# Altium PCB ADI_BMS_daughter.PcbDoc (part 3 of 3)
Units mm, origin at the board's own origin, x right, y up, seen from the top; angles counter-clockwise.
Board outline 140 x 50 mm, 4 copper layers (Top Layer, Layer 1, Layer 2, Bottom Layer), stack 1.586 mm thick; 306 components, 232 nets, 866 pads, 333 vias.
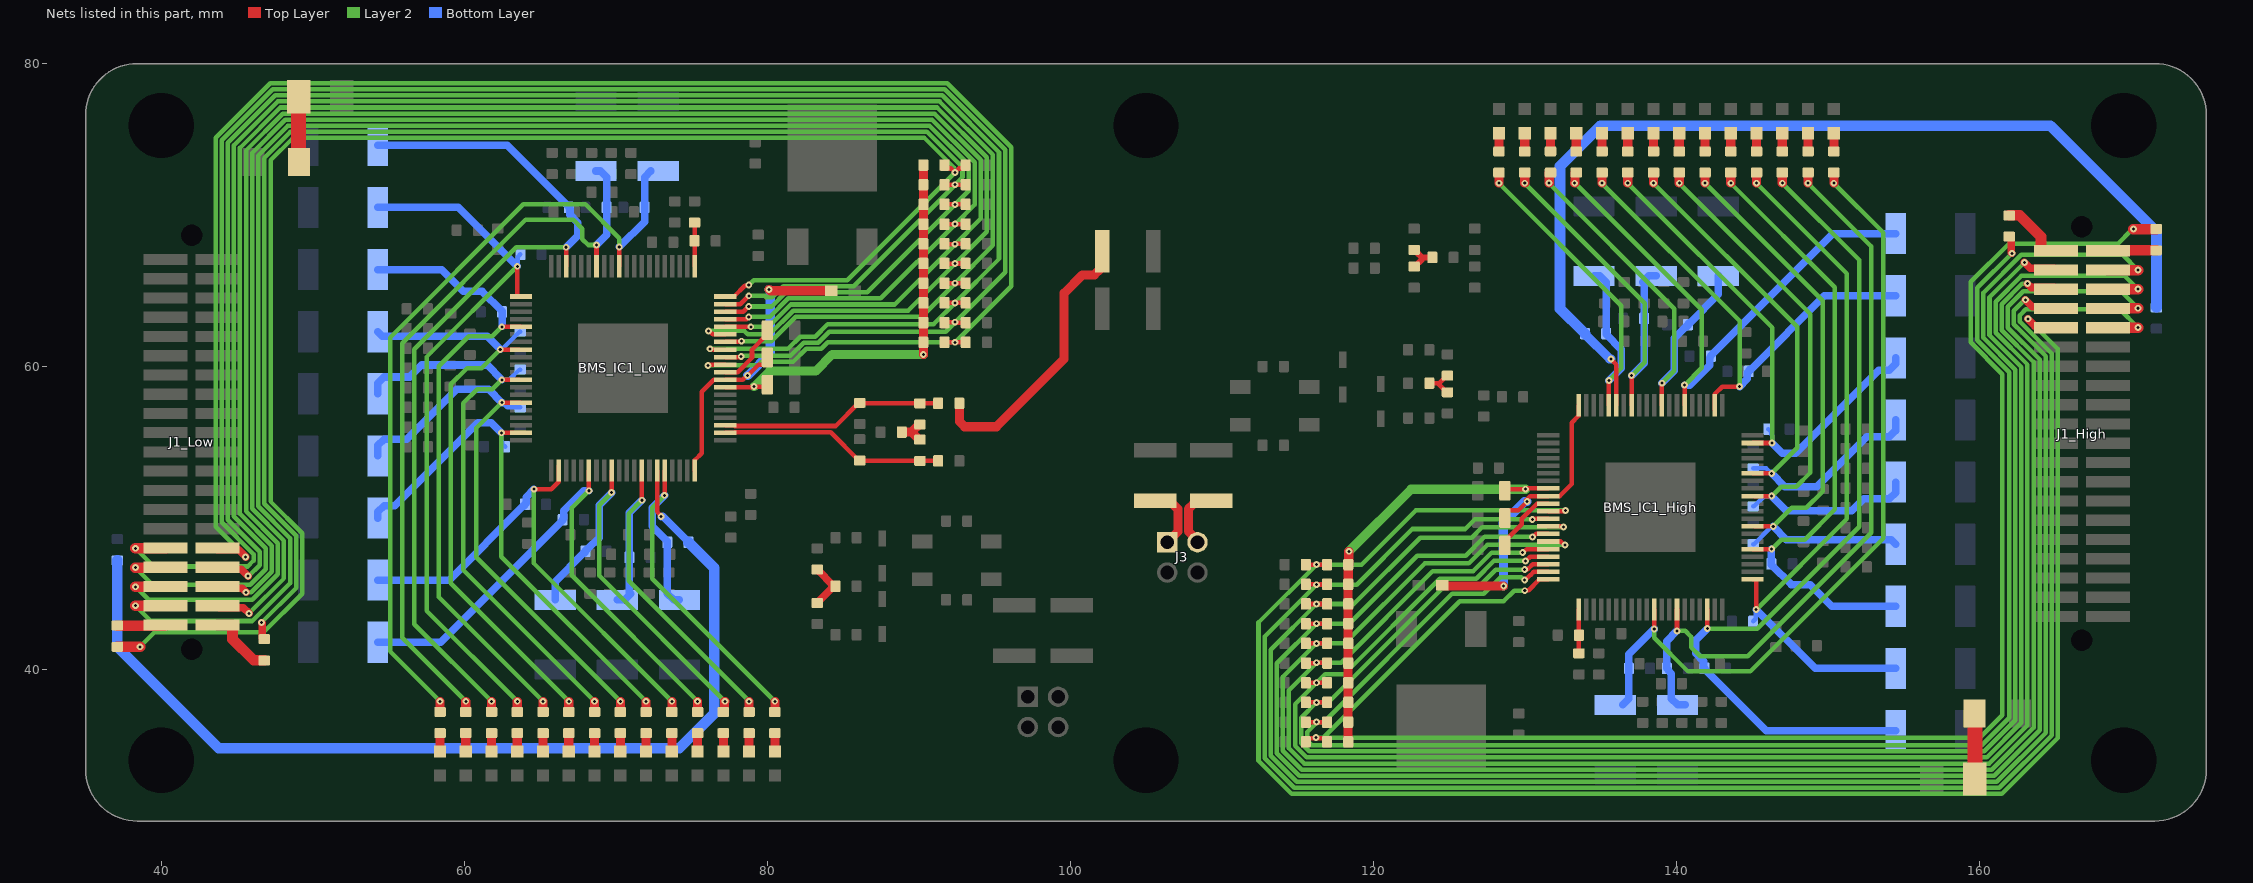
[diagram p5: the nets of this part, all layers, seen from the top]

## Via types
v1: diameter 0.45, hole 0.2, Top Layer to Bottom Layer, tented both sides, 226 vias
v2: diameter 0.5, hole 0.2, Top Layer to Bottom Layer, tented both sides, 105 vias
v3: diameter 2, hole 0.5, Top Layer to Bottom Layer, tented both sides, 2 vias

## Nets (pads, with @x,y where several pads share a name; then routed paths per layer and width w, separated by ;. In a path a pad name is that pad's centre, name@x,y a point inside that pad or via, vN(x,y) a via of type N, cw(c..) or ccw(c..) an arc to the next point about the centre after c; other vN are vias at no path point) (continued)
IB_Low_Intr_P: C55.2 R76.1 | length 18.7
  Top Layer w0.6: R76.1@92.679,57.571 92.679,56.374 93.03,56.022 95.122,56.022 99.598,60.498 99.598,64.841 100.808,66.051 101.597,66.051 101.948,66.402 101.948,67.423 C55.2@102.125,67.6
IB_Low_N: BMS_IC1_Low.62 C52.1 R73.1 R75.2 | length 14.9
  Top Layer w0.3: BMS_IC1_Low.62@77.217,55.621 77.804,55.621 77.853,55.671 84.18,55.671 86.05,53.8 C52.1@86.1,53.8 86.114,53.786 90.064,53.786 R73.1@90.079,53.771 R75.2@91.279,53.771
IB_Low_P: BMS_IC1_Low.63 C53.2 R74.2 R76.2 | length 14.7
  Top Layer w0.3: BMS_IC1_Low.63@77.217,56.121 77.804,56.121 77.853,56.072 84.522,56.072 86.05,57.6 C53.2@86.1,57.6 86.114,57.586 90.064,57.586 R74.2@90.079,57.571 R76.2@91.279,57.571
IB_Out_N: C60.2 J3.1 | length 4.2
  Top Layer w0.6: C60.2@105.6,51.125 105.777,50.948 106.749,50.948 107.1,50.597 107.1,49.1 J3.1@106.4,48.4
IB_Out_P: C62.2 J3.3 | length 4.2
  Top Layer w0.6: J3.3@108.4,48.4 108.4,48.528 107.802,49.126 107.802,50.597 108.153,50.948 109.123,50.948 C62.2@109.3,51.125
NetC48_1: C48.1 R68.1 R70.2 | length 3.1
  Top Layer w0.5: R70.2@83.3,44.4 83.35,44.4 83.43,44.48 83.43,44.53 84.27,45.37 84.27,45.63 83.43,46.47 83.43,46.52 83.35,46.6 R68.1@83.3,46.6
NetC51_2: C51.2 R73.2 R74.1 | length 2
  Top Layer w0.6: C51.2@88.879,55.671 89.609,55.671 ; 89.609,55.591 90.029,55.171 R73.2@90.079,55.171 ; 89.609,55.751 90.029,56.171 R74.1@90.079,56.171
NetC56_1: C56.1 R79.2 R80.2 | length 2.3
  Top Layer w0.4: R80.2@122.7,66.6 122.75,66.6 123.2,67.05 123.2,67.2 ; R79.2@122.7,67.7 122.75,67.7 122.966,67.484 122.966,67.434 123.2,67.2 ; C56.1@123.9,67.2 123.2,67.2
NetC61_1: C61.1 R82.1 R85.2 | length 2.5
  Top Layer w0.3: C61.1@123.7,58.9 124.2,58.9 ; R85.2@124.9,58.3 124.85,58.3 124.25,58.9 124.2,58.9 ; R82.1@124.9,59.4 124.85,59.4 124.35,58.9 124.2,58.9
  Top Layer w0.5: C61.1@123.7,58.9 C61.1@123.78,58.82
NetD1_High_1: D1_High.1 R42_High.1 | length 1.2
  Top Layer w0.6: R42_High.1@128.3,74.2 D1_High.1@128.3,75.4
NetD1_Low_1: D1_Low.1 R42_Low.1 | length 1.2
  Top Layer w0.6: D1_Low.1@80.5,34.6 R42_Low.1@80.5,35.8
NetD2_High_1: D2_High.1 R43_High.1 | length 1.2
  Top Layer w0.6: R43_High.1@130,74.2 D2_High.1@130,75.4
NetD2_Low_1: D2_Low.1 R43_Low.1 | length 1.2
  Top Layer w0.6: D2_Low.1@78.8,34.6 R43_Low.1@78.8,35.8
NetD3_High_1: D3_High.1 R44_High.1 | length 1.2
  Top Layer w0.6: R44_High.1@131.7,74.2 D3_High.1@131.7,75.4
NetD3_Low_1: D3_Low.1 R44_Low.1 | length 1.2
  Top Layer w0.6: D3_Low.1@77.1,34.6 R44_Low.1@77.1,35.8
NetD4_High_1: D4_High.1 R45_High.1 | length 1.2
  Top Layer w0.6: R45_High.1@133.4,74.2 D4_High.1@133.4,75.4
NetD4_Low_1: D4_Low.1 R45_Low.1 | length 1.2
  Top Layer w0.6: D4_Low.1@75.4,34.6 R45_Low.1@75.4,35.8
NetD5_High_1: D5_High.1 R46_High.1 | length 1.2
  Top Layer w0.6: R46_High.1@135.1,74.2 D5_High.1@135.1,75.4
NetD5_Low_1: D5_Low.1 R46_Low.1 | length 1.2
  Top Layer w0.6: D5_Low.1@73.7,34.6 R46_Low.1@73.7,35.8
NetD6_High_1: D6_High.1 R47_High.1 | length 1.2
  Top Layer w0.6: R47_High.1@136.8,74.2 D6_High.1@136.8,75.4
NetD6_Low_1: D6_Low.1 R47_Low.1 | length 1.2
  Top Layer w0.6: D6_Low.1@72,34.6 R47_Low.1@72,35.8
NetD7_High_1: D7_High.1 R48_High.1 | length 1.2
  Top Layer w0.6: R48_High.1@138.5,74.2 D7_High.1@138.5,75.4
NetD7_Low_1: D7_Low.1 R48_Low.1 | length 1.2
  Top Layer w0.6: D7_Low.1@70.3,34.6 R48_Low.1@70.3,35.8
NetD8_High_1: D8_High.1 R56_High.1 | length 1.2
  Top Layer w0.6: R56_High.1@140.2,74.2 D8_High.1@140.2,75.4
NetD8_Low_1: D8_Low.1 R56_Low.1 | length 1.2
  Top Layer w0.6: D8_Low.1@68.6,34.6 R56_Low.1@68.6,35.8
NetD9_High_1: D9_High.1 R57_High.1 | length 1.2
  Top Layer w0.6: R57_High.1@141.9,74.2 D9_High.1@141.9,75.4
NetD9_Low_1: D9_Low.1 R57_Low.1 | length 1.2
  Top Layer w0.6: D9_Low.1@66.9,34.6 R57_Low.1@66.9,35.8
NetD10_High_1: D10_High.1 R58_High.1 | length 1.2
  Top Layer w0.6: R58_High.1@143.6,74.2 D10_High.1@143.6,75.4
NetD10_Low_1: D10_Low.1 R58_Low.1 | length 1.2
  Top Layer w0.6: D10_Low.1@65.2,34.6 R58_Low.1@65.2,35.8
NetD11_High_1: D11_High.1 R59_High.1 | length 1.2
  Top Layer w0.6: R59_High.1@145.3,74.2 D11_High.1@145.3,75.4
NetD11_Low_1: D11_Low.1 R59_Low.1 | length 1.2
  Top Layer w0.6: D11_Low.1@63.5,34.6 R59_Low.1@63.5,35.8
NetD12_High_1: D12_High.1 R60_High.1 | length 1.2
  Top Layer w0.6: R60_High.1@147,74.2 D12_High.1@147,75.4
NetD12_Low_1: D12_Low.1 R60_Low.1 | length 1.2
  Top Layer w0.6: D12_Low.1@61.8,34.6 R60_Low.1@61.8,35.8
NetD13_High_1: D13_High.1 R61_High.1 | length 1.2
  Top Layer w0.6: R61_High.1@148.7,74.2 D13_High.1@148.7,75.4
NetD13_Low_1: D13_Low.1 R61_Low.1 | length 1.2
  Top Layer w0.6: D13_Low.1@60.1,34.6 R61_Low.1@60.1,35.8
NetD14_High_1: D14_High.1 R62_High.1 | length 1.2
  Top Layer w0.6: R62_High.1@150.4,74.2 D14_High.1@150.4,75.4
NetD14_Low_1: D14_Low.1 R62_Low.1 | length 1.2
  Top Layer w0.6: D14_Low.1@58.4,34.6 R62_Low.1@58.4,35.8
NetD15_High_1: D15_High.1 R63_High.2 | length 4.3
  Top Layer w1: D15_High.1@159.704,32.771 159.716,32.784 159.716,37.059 R63_High.2@159.729,37.071
NetD15_Low_1: D15_Low.1 R63_Low.2 | length 4.3
  Top Layer w1: R63_Low.2@49.05,73.5 49.062,73.512 49.062,77.787 D15_Low.1@49.075,77.8
S1N_High: BMS_IC1_High.55 C25_High.1 R34_High.1 | length 65.8
  Top Layer w0.3: v1(135.7,60.5) 135.7,60.459 136.054,60.105 136.054,58.654 136.05,58.65 BMS_IC1_High.55@136.05,57.438
  Bottom Layer w0.6: C25_High.1@133.979,62.171 133.979,62.121 135.6,60.5 v1(135.7,60.5)
  Bottom Layer w0.7: C25_High.1@133.979,62.171 133.959,62.191 133.959,62.201 133.939,62.221 133.929,62.221 132.329,63.821 132.329,73.229 135,75.9 164.7,75.9 171.7,68.9 R34_High.1@171.7,63.9
S1N_Low: BMS_IC1_Low.55 C25_Low.1 R34_Low.1 | length 66.5
  Top Layer w0.3: BMS_IC1_Low.55@72.729,53.133 72.729,51.712 72.725,51.708 72.725,50.416 73,50.141 v1(73,50.1)
  Bottom Layer w0.5: v1(73,50.1) 73.1,50.1 74.67,48.53 74.72,48.53 74.8,48.45 C25_Low.1@74.8,48.4
  Bottom Layer w0.7: R34_Low.1@37.1,47.2 37.1,41.5 43.8,34.8 74.2,34.8 76.5,37.1 76.5,46.7 74.85,48.35 74.84,48.35 74.82,48.37 74.82,48.38 C25_Low.1@74.8,48.4
S1P_High: BMS_IC1_High.56 C25_High.2 R35_High.2 R42_High.2 | length 27.5
  Top Layer w0.3: BMS_IC1_High.56@135.55,57.438 135.55,59.069 v1(135.552,59.071)
  Top Layer w0.6: v1(128.3,72.1) R42_High.2@128.3,72.8
  Layer 2 w0.3: v1@128.251,72.149 136.379,64.021 136.379,59.898 v1(135.552,59.071)
  Bottom Layer w0.5: R35_High.2@134.679,65.877 R35_High.2@134.579,65.977 134.964,65.977 135.379,65.562 C25_High.2@135.379,62.171 135.379,62.121 136.379,61.121 136.379,59.898 v1(135.552,59.071)
S1P_Low: BMS_IC1_Low.56 C25_Low.2 R35_Low.2 R42_Low.2 | length 27.9
  Top Layer w0.3: v1(73.227,51.5) 73.229,51.502 BMS_IC1_Low.56@73.229,53.133
  Top Layer w0.6: R42_Low.2@80.5,37.2 v1(80.5,37.9)
  Layer 2 w0.3: v1(73.227,51.5) 72.4,50.673 72.4,46 v1(80.5,37.9)
  Bottom Layer w0.5: v1(73.227,51.5) 72.4,50.673 72.4,50.351 72.398,50.349 72.398,49.851 72.4,49.849 72.4,49.45 73.4,48.45 C25_Low.2@73.4,48.4 73.4,45.009 73.815,44.594 R35_Low.2@74.2,44.594
S2P_High: BMS_IC1_High.53 C26_High.2 R36_High.2 R43_High.2 | length 27.1
  Top Layer w0.3: BMS_IC1_High.53@137.05,57.438 137.05,59.398 v1(137.052,59.4)
  Top Layer w0.6: v1(130,72.1) R43_High.2@130,72.8
  Layer 2 w0.3: v1@129.995,72.105 137.929,64.171 137.929,60.277 v1(137.052,59.4)
  Bottom Layer w0.5: v1(137.052,59.4) 137.879,60.227 C26_High.2@137.879,63.171 137.879,65.662 R36_High.2@138.194,65.977 ; R36_High.2@137.779,65.562 R36_High.2@138.194,65.977 ; R36_High.2@138.679,65.977 R36_High.2@138.194,65.977
S2P_Low: BMS_IC1_Low.53 C26_Low.2 R36_Low.2 R43_Low.2 | length 27.7
  Top Layer w0.3: v1(71.727,51.171) 71.729,51.173 BMS_IC1_Low.53@71.729,53.133
  Top Layer w0.6: R43_Low.2@78.8,37.2 v1(78.8,37.9)
  Layer 2 w0.3: v1(71.727,51.171) 70.85,50.295 70.85,45.85 v1(78.8,37.9)
  Bottom Layer w0.5: R36_Low.2@70.1,44.594 R36_Low.2@70.585,44.594 ; R36_Low.2@71,45.009 R36_Low.2@70.585,44.594 ; v1(71.727,51.171) 70.9,50.345 C26_Low.2@70.9,47.4 70.9,44.909 R36_Low.2@70.585,44.594
S3P_High: BMS_IC1_High.49 C27_High.2 R37_High.2 R44_High.2 | length 27.8
  Top Layer w0.3: BMS_IC1_High.49@139.05,57.438 139.05,58.894 v1(139.052,58.896)
  Top Layer w0.6: v1(131.604,72.106) 131.62,72.122 131.62,72.77 131.65,72.8 R44_High.2@131.7,72.8
  Layer 2 w0.3: v1@131.598,72.102 139.879,63.821 139.879,59.723 v1(139.052,58.896)
  Bottom Layer w0.5: v1(139.052,58.896) 139.879,59.723 139.879,61.871 140.649,62.641 140.699,62.641 C27_High.2@140.779,62.721 ; C27_High.2@140.779,62.771 140.779,62.821 140.859,62.901 140.909,62.901 142.779,64.771 R37_High.2@142.779,65.977
S3P_Low: BMS_IC1_Low.49 C27_Low.2 R37_Low.2 R44_Low.2 | length 28.4
  Top Layer w0.3: v1(69.727,51.675) 69.729,51.677 BMS_IC1_Low.49@69.729,53.133
  Top Layer w0.6: R44_Low.2@77.1,37.2 77.15,37.2 77.18,37.23 77.18,37.878 v1(77.202,37.9)
  Layer 2 w0.3: v1(69.727,51.675) 68.9,50.848 68.9,46.202 v1(77.202,37.9)
  Bottom Layer w0.5: R37_Low.2@66,44.594 66,45.8 67.87,47.67 67.92,47.67 68,47.75 C27_Low.2@68,47.8 ; C27_Low.2@68,47.85 68.08,47.93 68.13,47.93 68.9,48.7 68.9,50.848 v1(69.727,51.675)
S4P_High: BMS_IC1_High.46 C28_High.2 R38_High.2 R45_High.2 | length 37.8
  Top Layer w0.3: BMS_IC1_High.46@140.55,57.438 v1(140.552,58.771) v1(140.552,58.771)
  Top Layer w0.6: v1(133.298,72.1) 133.32,72.122 133.32,72.77 133.37,72.77 R45_High.2@133.4,72.8
  Layer 2 w0.3: v1(133.298,72.1) 133.325,72.1 141.689,63.736 141.689,59.909 v1(140.552,58.771)
  Bottom Layer w0.5: v1(140.552,58.771) 140.879,58.771 142.198,60.091 142.198,60.591 C28_High.2@142.279,60.671 142.279,60.721 150.329,68.771 R38_High.2@154.485,68.771
S4P_Low: BMS_IC1_Low.46 C28_Low.2 R38_Low.2 R45_Low.2 | length 38.2
  Top Layer w0.3: v1(68.227,51.8) 68.229,51.802 BMS_IC1_Low.46@68.229,53.133
  Top Layer w0.6: R45_Low.2@75.4,37.2 v1(75.4,37.9)
  Layer 2 w0.3: v1(68.227,51.8) 67.089,50.663 67.089,46.211 v1(75.4,37.9)
  Bottom Layer w0.5: R38_Low.2@54.294,41.8 58.45,41.8 66.5,49.85 C28_Low.2@66.5,49.9 66.58,49.98 66.58,50.48 67.9,51.8 v1(68.227,51.8)
S5P_High: BMS_IC1_High.42 C29_High.2 R39_High.2 R46_High.2 | length 33.8
  Top Layer w0.3: BMS_IC1_High.42@142.55,57.138 142.55,58.181 143.04,58.671 v1(144.179,58.671)
  Top Layer w0.6: v1(135.1,72.1) R46_High.2@135.1,72.8
  Layer 2 w0.3: v1@135.092,72.108 144.179,63.021 v1(144.179,58.671)
  Bottom Layer w0.5: v1(144.179,58.671) 144.699,59.191 144.699,59.591 C29_High.2@144.779,59.671 144.779,59.721 144.859,59.801 144.909,59.801 149.779,64.671 R39_High.2@154.485,64.671
S5P_Low: BMS_IC1_Low.42 C29_Low.2 R39_Low.2 R46_Low.2 | length 34.4
  Top Layer w0.3: v1(64.6,51.9) 65.739,51.9 66.229,52.39 BMS_IC1_Low.42@66.229,53.433
  Top Layer w0.6: R46_Low.2@73.7,37.2 v1(73.7,37.9)
  Layer 2 w0.3: v1(64.6,51.9) 64.6,47 v1(73.7,37.9)
  Bottom Layer w0.5: R39_Low.2@54.294,45.9 59,45.9 63.87,50.77 63.92,50.77 64,50.85 C29_Low.2@64,50.9 64.08,50.98 64.08,51.38 v1(64.6,51.9)
S6P_High: BMS_IC1_High.39 C30_High.2 R40_High.2 R47_High.2 | length 35.4
  Top Layer w0.3: BMS_IC1_High.39@145.038,54.95 146.327,54.95 v1(146.329,54.948)
  Top Layer w0.6: v1(136.8,72.1) R47_High.2@136.8,72.8
  Layer 2 w0.3: v1@136.827,72.073 146.329,62.571 v1(146.329,54.948)
  Bottom Layer w0.3: C30_High.2@146.079,55.871 146.259,55.691 146.259,55.535 146.329,55.466 v1(146.329,54.948)
  Bottom Layer w0.5: v1(146.329,54.948) 147.005,54.271 147.879,54.271 153.363,59.755 154.07,59.755 154.485,60.17 R40_High.2@154.485,60.571
S6P_Low: BMS_IC1_Low.39 C30_Low.2 R40_Low.2 R47_Low.2 | length 36
  Top Layer w0.3: v1(62.45,55.623) 62.452,55.621 BMS_IC1_Low.39@63.741,55.621
  Top Layer w0.6: R47_Low.2@72,37.2 v1(72,37.9)
  Layer 2 w0.3: v1(62.45,55.623) 62.45,47.45 v1(72,37.9)
  Bottom Layer w0.3: v1(62.45,55.623) 62.45,55.106 62.52,55.036 62.52,54.88 C30_Low.2@62.7,54.7
  Bottom Layer w0.5: R40_Low.2@54.294,50 54.294,50.401 54.709,50.816 55.416,50.816 60.9,56.3 61.773,56.3 v1(62.45,55.623)
S7P_High: BMS_IC1_High.35 C31_High.2 R41_High.2 R48_High.2 | length 37.8
  Top Layer w0.3: BMS_IC1_High.35@145.038,52.95 v1(146.3,52.948) v1(146.3,52.948)
  Top Layer w0.6: v1(138.5,72.1) R48_High.2@138.5,72.8
  Layer 2 w0.3: v1@138.549,72.051 147.981,62.619 147.981,54.629 v1(146.3,52.948)
  Bottom Layer w0.3: C31_High.2@145.079,53.271 145.936,53.271 146.259,52.948 v1(146.3,52.948)
  Bottom Layer w0.5: v1(146.3,52.948) 147.176,52.071 149.279,52.071 152.569,55.361 154.07,55.361 154.485,55.776 R41_High.2@154.485,56.471
S7P_Low: BMS_IC1_Low.35 C31_Low.2 R41_Low.2 R48_Low.2 | length 38.5
  Top Layer w0.3: v1(62.479,57.623) 62.481,57.621 BMS_IC1_Low.35@63.741,57.621
  Top Layer w0.6: R48_Low.2@70.3,37.2 v1(70.3,37.9)
  Layer 2 w0.3: v1(62.479,57.623) 60.798,55.942 60.798,47.402 v1(70.3,37.9)
  Bottom Layer w0.3: v1(62.479,57.623) 62.52,57.623 62.843,57.3 C31_Low.2@63.7,57.3
  Bottom Layer w0.5: R41_Low.2@54.294,54.1 54.294,54.795 54.709,55.21 56.21,55.21 59.5,58.5 61.602,58.5 v1(62.479,57.623)
S8P_High: BMS_IC1_High.32 C32_High.2 R49_High.2 R56_High.2 | length 39
  Top Layer w0.3: BMS_IC1_High.32@145.138,51.45 146.298,51.45 v1(146.3,51.448)
  Top Layer w0.6: v1(140.2,72.1) R56_High.2@140.2,72.8
  Layer 2 w0.3: v1@140.208,72.092 148.858,63.442 148.858,53.001 147.929,52.071 146.923,52.071 v1(146.3,51.448)
  Bottom Layer w0.3: C32_High.2@145.079,50.771 145.128,50.771 145.805,51.448 v1(146.3,51.448)
  Bottom Layer w0.5: v1(146.3,51.448) 147.277,50.471 151.579,50.471 152.369,51.261 154.07,51.261 154.485,51.676 R49_High.2@154.485,52.371
S8P_Low: BMS_IC1_Low.32 C32_Low.2 R49_Low.2 R56_Low.2 | length 39.6
  Top Layer w0.3: v1(62.479,59.123) 62.481,59.121 BMS_IC1_Low.32@63.641,59.121
  Top Layer w0.6: R56_Low.2@68.6,37.2 v1(68.6,37.9)
  Layer 2 w0.3: v1(62.479,59.123) 61.855,58.5 60.85,58.5 59.921,57.571 59.921,46.579 v1(68.6,37.9)
  Bottom Layer w0.3: v1(62.479,59.123) 62.974,59.123 63.65,59.8 C32_Low.2@63.7,59.8
  Bottom Layer w0.5: R49_Low.2@54.294,58.2 54.294,58.895 54.709,59.31 56.41,59.31 57.2,60.1 61.502,60.1 v1(62.479,59.123)
S9P_High: BMS_IC1_High.28 C33_High.2 R50_High.2 R57_High.2 | length 40.1
  Top Layer w0.3: BMS_IC1_High.28@145.138,49.45 146.398,49.45 v1(146.403,49.445)
  Top Layer w0.6: v1(141.9,72.1) R57_High.2@141.9,72.8
  Layer 2 w0.3: v1@141.905,72.095 149.661,64.339 149.661,51.754 148.579,50.671 147.63,50.671 v1(146.403,49.445)
  Bottom Layer w0.3: C33_High.2@145.079,48.271 145.128,48.271 146.273,49.416 146.375,49.416 v1(146.403,49.445)
  Bottom Layer w0.5: v1(146.403,49.445) 147.277,48.571 154.185,48.571 R50_High.2@154.485,48.271
S9P_Low: BMS_IC1_Low.28 C33_Low.2 R50_Low.2 R57_Low.2 | length 40.7
  Top Layer w0.3: v1(62.375,61.127) 62.381,61.121 BMS_IC1_Low.28@63.641,61.121
  Top Layer w0.6: R57_Low.2@66.9,37.2 v1(66.9,37.9)
  Layer 2 w0.3: v1(62.375,61.127) 61.149,59.9 60.2,59.9 59.118,58.818 59.118,45.682 v1(66.9,37.9)
  Bottom Layer w0.3: v1(62.375,61.127) 62.404,61.155 62.506,61.155 63.65,62.3 C33_Low.2@63.7,62.3
  Bottom Layer w0.5: R50_Low.2@54.294,62.3 54.594,62 61.502,62 v1(62.375,61.127)
S10P_High: BMS_IC1_High.25 C34_High.2 R51_High.2 R58_High.2 | length 42
  Top Layer w0.3: BMS_IC1_High.25@145.038,47.95 146.298,47.95 v1(146.3,47.948)
  Top Layer w0.6: v1(143.6,72.1) R58_High.2@143.6,72.8
  Layer 2 w0.3: v1@143.585,72.115 150.464,65.236 150.464,50.564 148.471,48.571 146.923,48.571 v1(146.3,47.948)
  Bottom Layer w0.5: v1@146.279,47.927 C34_High.2@146.279,46.971 146.279,46.922 147.609,45.591 148.859,45.591 150.279,44.171 R51_High.2@154.485,44.171
S10P_Low: BMS_IC1_Low.25 C34_Low.2 R51_Low.2 R58_Low.2 | length 42.5
  Top Layer w0.3: v1(62.479,62.623) 62.481,62.621 BMS_IC1_Low.25@63.741,62.621
  Top Layer w0.6: R58_Low.2@65.2,37.2 v1(65.2,37.9)
  Layer 2 w0.3: v1(62.479,62.623) 61.855,62 60.307,62 58.314,60.007 58.314,44.786 v1(65.2,37.9)
  Bottom Layer w0.5: R51_Low.2@54.294,66.4 58.5,66.4 59.92,64.98 61.17,64.98 62.5,63.65 C34_Low.2@62.5,63.6 v1@62.5,62.645
S11P_High: BMS_IC1_High.21 C35_High.2 R52_High.2 R59_High.2 | length 47.7
  Top Layer w0.3: BMS_IC1_High.21@145.038,45.95 145.279,45.95 v1(145.279,43.955)
  Top Layer w0.6: v1(145.3,72.1) R59_High.2@145.3,72.8
  Layer 2 w0.3: v1(145.279,43.955) 151.268,49.944 151.268,66.133 v1(145.3,72.1)
  Bottom Layer w0.3: C35_High.2@145.079,43.171 145.15,43.243 145.25,43.343 145.25,43.927 v1(145.279,43.955)
  Bottom Layer w0.5: v1(145.279,43.955) 149.163,40.071 R52_High.2@154.485,40.071
S11P_Low: BMS_IC1_Low.21 C35_Low.2 R52_Low.2 R59_Low.2 | length 48.4
  Top Layer w0.3: v1(63.5,66.616) 63.5,64.621 BMS_IC1_Low.21@63.741,64.621
  Top Layer w0.6: R59_Low.2@63.5,37.2 v1(63.5,37.9)
  Layer 2 w0.3: v1(63.5,37.9) 57.511,43.889 57.511,60.627 v1(63.5,66.616)
  Bottom Layer w0.3: v1(63.5,66.616) 63.529,66.645 63.529,67.229 C35_Low.2@63.7,67.4 C35_Low.2@63.629,67.329
  Bottom Layer w0.5: R52_Low.2@54.294,70.5 59.616,70.5 v1(63.5,66.616)
S12P_High: BMS_IC1_High.18 C36_High.2 R53_High.2 R60_High.2 | length 57
  Top Layer w0.3: v1(142.048,42.7) 142.05,42.702 BMS_IC1_High.18@142.05,43.962
  Top Layer w0.6: v1(147,72.1) R60_High.2@147,72.8
  Layer 2 w0.3: v1(142.048,42.7) 145.343,42.7 152.071,49.428 152.071,67.029 v1(147,72.1)
  Bottom Layer w0.5: C36_High.2@141.798,40.152 141.798,40.552 141.279,41.071 141.279,41.931 v1(142.048,42.7) ; C36_High.2@141.879,40.071 141.879,40.022 145.929,35.971 R53_High.2@154.485,35.971
S12P_Low: BMS_IC1_Low.18 C36_Low.2 R53_Low.2 R60_Low.2 | length 57.5
  Top Layer w0.3: BMS_IC1_Low.18@66.729,66.609 66.729,67.869 v1(66.731,67.871)
  Top Layer w0.6: R60_Low.2@61.8,37.2 v1(61.8,37.9)
  Layer 2 w0.3: v1(61.8,37.9) 56.708,42.992 56.708,61.143 63.436,67.871 v1(66.731,67.871)
  Bottom Layer w0.5: R53_Low.2@54.294,74.6 62.85,74.6 66.9,70.55 C36_Low.2@66.9,70.5 ; v1(66.731,67.871) 67.5,68.641 67.5,69.5 66.98,70.02 C36_Low.2@66.98,70.42
S13P_High: BMS_IC1_High.14 C37_High.2 R54_High.2 R61_High.2 | length 50.2
  Top Layer w0.3: v1(140.048,42.55) 140.05,42.552 BMS_IC1_High.14@140.05,43.962
  Top Layer w0.6: v1(148.7,72.1) R61_High.2@148.7,72.8
  Layer 2 w0.3: v1(140.048,42.55) 140.6,42.55 140.979,42.171 140.979,41.471 141.579,40.871 144.711,40.871 152.874,49.034 152.874,67.926 v1(148.7,72.1)
  Bottom Layer w0.5: v1(140.048,42.55) 139.377,41.879 139.377,40.073 C37_High.2@139.379,40.071 139.459,39.991 139.459,39.941 139.679,39.721 139.679,38.08 140.094,37.665 R54_High.2@140.579,37.665
S13P_Low: BMS_IC1_Low.14 C37_Low.2 R54_Low.2 R61_Low.2 | length 50.4
  Top Layer w0.3: BMS_IC1_Low.14@68.729,66.609 68.729,68.019 v1(68.731,68.021)
  Top Layer w0.6: R61_Low.2@60.1,37.2 v1(60.1,37.9)
  Layer 2 w0.3: v1(60.1,37.9) 55.905,42.095 55.905,61.537 64.068,69.7 67.2,69.7 67.8,69.1 67.8,68.4 68.179,68.021 v1(68.731,68.021)
  Bottom Layer w0.5: R54_Low.2@68.685,72.906 68.985,72.906 69.4,72.491 69.4,68.691 v1(68.731,68.021)
S14P_High: BMS_IC1_High.11 C38_High.2 R55_High.2 R62_High.2 | length 52.9
  Top Layer w0.3: v1(138.548,42.675) 138.55,42.677 BMS_IC1_High.11@138.55,43.962
  Top Layer w0.6: v1(150.4,72.1) R62_High.2@150.4,72.8
  Layer 2 w0.3: v1(138.548,42.675) 138.548,42.102 140.779,39.871 144.879,39.871 153.677,48.67 153.677,68.823 v1(150.4,72.1)
  Bottom Layer w0.5: R55_High.2@136.479,37.665 136.879,38.065 C38_High.2@136.879,40.071 136.879,41.006 v1(138.548,42.675)
S14P_Low: BMS_IC1_Low.11 C38_Low.2 R55_Low.2 R62_Low.2 | length 53.5
  Top Layer w0.3: BMS_IC1_Low.11@70.229,66.609 70.229,67.894 v1(70.231,67.896)
  Top Layer w0.6: R62_Low.2@58.4,37.2 v1(58.4,37.9)
  Layer 2 w0.3: v1(58.4,37.9) 55.102,41.198 55.102,61.902 63.9,70.7 68,70.7 70.231,68.469 v1(70.231,67.896)
  Bottom Layer w0.5: v1(70.231,67.896) 71.9,69.566 71.9,72.506 R55_Low.2@72.3,72.906
TEMP1_after_jumper_High: BMS_IC1_High.80 C1_High.1 R1_High.1 R3_High.1 | length 109.9
  Top Layer w0.3: C1_High.1@115.55,35.225 115.55,35.275 115.73,35.455 116.139,35.455 116.186,35.502 v1(116.227,35.502) 116.256,35.473 116.621,35.473 116.64,35.455 116.77,35.455 116.95,35.275 R3_High.1@116.95,35.225 ; v1(130,45.2) 130.029,45.229 130.253,45.229 130.974,45.95 BMS_IC1_High.80@131.562,45.95
  Top Layer w0.7: v1(170.179,69.071) R1_High.1@171.679,69.071
  Layer 2 w0.3: v1(116.227,35.502) 116.702,35.502 ; v1(130,45.2) 129.3,45.2 128.6,44.5 125.7,44.5 116.702,35.502 ; v1(170.179,69.071) 170.138,69.071 170.063,68.996 170.045,68.996 169.165,68.116 161.971,68.116 159.438,65.583 159.438,61.591 161.528,59.501 161.528,36.987 160.043,35.502 116.702,35.502
TEMP1_after_jumper_Low: BMS_IC1_Low.80 C1_Low.1 R1_Low.1 R3_Low.1 | length 110.5
  Top Layer w0.3: BMS_IC1_Low.80@77.217,64.621 77.804,64.621 78.526,65.343 78.75,65.343 v1(78.779,65.371) ; R3_Low.1@91.7,73.3 91.7,73.25 91.88,73.07 92.136,73.07 v1@92.387,72.819 ; C1_Low.1@93.1,73.3 93.1,73.25 92.92,73.07 92.638,73.07 v1@92.387,72.819 ; v1@92.387,72.819 v1(92.387,72.8) v1@92.387,72.819
  Top Layer w0.7: R1_Low.1@37.1,41.5 v1(38.6,41.5)
  Layer 2 w0.3: v1(38.6,41.5) 39.555,42.455 46.749,42.455 49.305,45.011 49.305,49.003 47.214,51.093 47.214,73.607 48.695,75.087 90.376,75.087 92.358,73.105 92.358,72.829 v1(92.387,72.8) 85.287,65.7 79.107,65.7 v1(78.779,65.371)
TEMP1_High: J1_High.39 R1_High.2 | length 3.2
  Top Layer w0.7: J1_High.39@168.529,67.671 R1_High.2@171.679,67.671
TEMP1_Low: J1_Low.39 R1_Low.2 | length 3.2
  Top Layer w0.7: R1_Low.2@37.1,42.9 J1_Low.39@40.25,42.9
TEMP2_after_jumper_High: BMS_IC1_High.79 C2_High.1 R2_High.1 R4_High.1 | length 103.4
  Top Layer w0.3: C2_High.1@115.55,36.525 v1(116.25,36.525) R4_High.1@116.95,36.525 ; v1(129.995,45.905) 130.036,45.905 130.399,46.268 130.415,46.268 130.597,46.45 BMS_IC1_High.79@131.562,46.45
  Top Layer w0.5: R2_High.1@161.979,68.571 162.028,68.571 162.109,68.491 162.109,67.521 v1(162.159,67.471)
  Layer 2 w0.3: v1(129.995,45.905) 129.954,45.905 129.759,46.1 128.4,46.1 127.3,45 125.2,45 116.725,36.525 v1(116.25,36.525) 116.25,36.484 115.64,35.875 115.64,35.31 115.95,35 160.168,35 161.979,36.811 161.979,59.632 159.876,61.735 159.876,65.188 v1(162.159,67.471)
TEMP2_after_jumper_Low: BMS_IC1_Low.79 C2_Low.1 R2_Low.1 R4_Low.1 | length 102.7
  Top Layer w0.3: BMS_IC1_Low.79@77.217,64.121 78.229,64.121 78.774,64.666 v1(78.784,64.666) ; R4_Low.1@91.7,72 v1(92.4,72) C2_Low.1@93.1,72
  Top Layer w0.5: v1(46.62,43.1) 46.67,43.05 46.67,42.08 46.75,42 R2_Low.1@46.8,42
  Layer 2 w0.3: v1(46.62,43.1) 48.903,45.383 48.903,48.837 46.8,50.94 46.8,73.76 48.529,75.489 90.542,75.489 92.889,73.142 92.889,72.489 v1(92.4,72) 85.698,65.298 81.059,65.298 80.333,64.573 79.917,64.573 79.824,64.666 v1(78.784,64.666)
TEMP2_High: J1_High.40 R2_High.2 | length 4.6
  Top Layer w0.7: R2_High.2@161.979,69.971 162.679,69.971 164.079,68.571 164.079,67.656 164.099,67.636 J1_High.40@165.064,67.636
TEMP2_Low: J1_Low.40 R2_Low.2 | length 4.6
  Top Layer w0.7: J1_Low.40@43.715,42.935 44.68,42.935 44.7,42.915 44.7,42 46.1,40.6 R2_Low.2@46.8,40.6
TEMP3_High: BMS_IC1_High.78 C3_High.1 J1_High.37 R5_High.1 | length 114.6
  Top Layer w0.3: C3_High.1@115.55,37.825 116.2,37.825 116.25,37.775 116.3,37.825 R5_High.1@116.95,37.825 R5_High.1@116.925,37.85 ; v1(129.999,46.596) 130.028,46.625 130.188,46.625 130.232,46.67 130.248,46.67 130.529,46.95 BMS_IC1_High.78@131.562,46.95
  Top Layer w0.7: J1_High.37@168.494,66.366 168.499,66.361 v1(170.479,66.361)
  Layer 2 w0.3: v1(129.999,46.596) 128.096,46.596 127,45.5 124.7,45.5 117.025,37.825 v1(116.25,37.825) 115.239,36.813 115.239,35.144 115.785,34.597 160.332,34.597 162.38,36.645 162.38,59.798 160.277,61.901 160.277,64.869 162.776,67.368 169.472,67.368 v1(170.479,66.361)
TEMP3_Low: BMS_IC1_Low.78 C3_Low.1 J1_Low.37 R5_Low.1 | length 114.1
  Top Layer w0.3: BMS_IC1_Low.78@77.217,63.621 78.404,63.621 78.744,63.961 v1(78.779,63.961) ; R5_Low.1@91.725,70.675 R5_Low.1@91.7,70.7 92.35,70.7 92.4,70.75 92.45,70.7 C3_Low.1@93.1,70.7
  Top Layer w0.7: v1(38.3,44.21) 40.28,44.21 J1_Low.37@40.285,44.205
  Layer 2 w0.3: v1(38.3,44.21) 39.307,43.203 46.003,43.203 48.502,45.702 48.502,48.67 46.398,50.773 46.398,73.927 48.362,75.89 90.708,75.89 93.29,73.308 93.29,71.59 v1(92.4,70.7) 86.597,64.897 81.225,64.897 80.29,63.961 v1(78.779,63.961)
TEMP4_High: BMS_IC1_High.77 C4_High.1 J1_High.38 R6_High.1 | length 108.6
  Top Layer w0.3: C4_High.1@115.55,39.125 v1(116.25,39.125) R6_High.1@116.95,39.125 ; v1(130.041,47.172) 130.081,47.172 130.359,47.45 BMS_IC1_High.77@131.562,47.45
  Top Layer w0.5: v1(162.984,66.866) 163.364,66.486 164.944,66.486 J1_High.38@165.064,66.366
  Layer 2 w0.3: v1(130.041,47.172) 127.972,47.172 126.8,46 124.4,46 118.1,39.7 116.825,39.7 v1(116.25,39.125) 114.837,37.712 114.837,34.977 115.619,34.195 160.499,34.195 162.782,36.478 162.782,59.964 160.679,62.067 160.679,64.561 v1(162.984,66.866)
TEMP4_Low: BMS_IC1_Low.77 C4_Low.1 J1_Low.38 R6_Low.1 | length 108.1
  Top Layer w0.3: BMS_IC1_Low.77@77.217,63.121 78.629,63.121 v1(78.779,63.271) ; R6_Low.1@91.7,69.4 v1(92.4,69.4) C4_Low.1@93.1,69.4
  Top Layer w0.5: J1_Low.38@43.715,44.205 43.835,44.085 45.415,44.085 v1(45.795,43.705)
  Layer 2 w0.3: v1(45.795,43.705) 48.1,46.01 48.1,48.504 45.997,50.607 45.997,74.093 48.196,76.292 90.875,76.292 93.692,73.475 93.692,70.692 v1(92.4,69.4) 87.495,64.495 81.391,64.495 80.167,63.271 v1(78.779,63.271)
TEMP5_High: BMS_IC1_High.76 C5_High.1 J1_High.35 R7_High.1 | length 117.7
  Top Layer w0.3: C5_High.1@115.55,40.425 116.225,40.425 v1(116.25,40.45) R7_High.1@116.95,40.45 ; v1(129.864,47.721) 129.904,47.721 130.133,47.95 BMS_IC1_High.76@131.562,47.95
  Top Layer w0.7: J1_High.35@168.494,65.096 168.509,65.111 v1(170.479,65.111)
  Layer 2 w0.3: v1(129.864,47.721) 127.829,47.721 126.608,46.5 123.932,46.5 117.882,40.45 v1(116.25,40.45) 114.435,38.635 114.435,34.811 115.453,33.794 160.665,33.794 163.184,36.312 163.184,60.131 161.08,62.234 161.08,64.281 162.776,65.977 169.613,65.977 v1(170.479,65.111)
TEMP5_Low: BMS_IC1_Low.76 C5_Low.1 J1_Low.35 R7_Low.1 | length 117.2
  Top Layer w0.3: BMS_IC1_Low.76@77.217,62.621 v1(78.915,62.621) ; R7_Low.1@91.7,68.075 v1(92.4,68.075) 92.425,68.1 C5_Low.1@93.1,68.1
  Top Layer w0.7: v1(38.3,45.46) 40.27,45.46 J1_Low.35@40.285,45.475
  Layer 2 w0.3: v1(38.3,45.46) 39.166,44.594 46.003,44.594 47.698,46.29 47.698,48.337 45.595,50.441 45.595,74.259 48.03,76.694 91.041,76.694 94.094,73.641 94.094,69.769 v1(92.4,68.075) 88.419,64.094 81.558,64.094 80.085,62.621 v1(78.915,62.621)
TEMP6_High: BMS_IC1_High.75 C6_High.1 J1_High.36 R8_High.1 | length 114
  Top Layer w0.3: C6_High.1@115.55,41.725 v1(116.25,41.725) 116.263,41.737 R8_High.1@116.937,41.737 ; R8_High.1@116.912,41.813 R8_High.1@116.925,41.825 ; BMS_IC1_High.75@131.562,48.45 132.381,48.45 132.609,48.223 v1(132.649,48.223)
  Top Layer w0.5: v1(163.179,65.475) 163.438,65.216 164.944,65.216 J1_High.36@165.064,65.096
  Layer 2 w0.3: v1(132.649,48.223) 127.523,48.223 126.3,47 123.4,47 118.125,41.725 v1(116.25,41.725) 114.034,39.509 114.034,34.644 115.286,33.392 160.831,33.392 163.585,36.146 163.585,60.297 161.482,62.4 161.482,64.115 162.842,65.475 v1(163.179,65.475)
TEMP6_Low: BMS_IC1_Low.75 C6_Low.1 J1_Low.36 R8_Low.1 | length 113.7
  Top Layer w0.3: v1(76.13,62.348) 76.17,62.348 76.397,62.121 BMS_IC1_Low.75@77.217,62.121 ; R8_Low.1@91.7,66.775 91.712,66.787 92.388,66.787 v1(92.4,66.8) C6_Low.1@93.1,66.8
  Top Layer w0.5: J1_Low.36@43.715,45.475 43.835,45.355 45.341,45.355 v1(45.6,45.096)
  Layer 2 w0.3: v1(45.6,45.096) 45.937,45.096 47.297,46.456 47.297,48.171 45.194,50.274 45.194,74.426 47.863,77.095 91.207,77.095 94.495,73.808 94.495,68.895 v1(92.4,66.8) 89.292,63.692 81.724,63.692 80.151,62.119 78.707,62.119 78.478,62.348 v1(76.13,62.348)
TEMP7_High: BMS_IC1_High.74 C7_High.1 J1_High.33 R9_High.1 | length 121.3
  Top Layer w0.3: C7_High.1@115.55,43.025 116.05,43.025 R9_High.1@116.95,43.025 ; v1(130.507,48.753) 130.548,48.753 130.745,48.95 BMS_IC1_High.74@131.562,48.95
  Top Layer w0.7: J1_High.33@168.494,63.826 168.513,63.845 v1(170.483,63.845)
  Layer 2 w0.3: v1(130.507,48.753) 127.348,48.753 126.095,47.5 122.9,47.5 118.425,43.025 v1(116.25,43.025) 113.632,40.407 113.632,34.478 115.12,32.99 160.998,32.99 163.987,35.979 163.987,60.463 161.883,62.566 161.883,63.949 162.908,64.973 169.355,64.973 v1(170.483,63.845)
TEMP7_Low: BMS_IC1_Low.74 C7_Low.1 J1_Low.33 R9_Low.1 | length 120.8
  Top Layer w0.3: BMS_IC1_Low.74@77.217,61.621 78.218,61.621 78.266,61.669 v1(78.306,61.669) ; R9_Low.1@91.7,65.5 92.6,65.5 C7_Low.1@93.1,65.5
  Top Layer w0.7: v1(38.296,46.726) 40.266,46.726 J1_Low.33@40.285,46.745
  Layer 2 w0.3: v1(38.296,46.726) 39.424,45.598 45.871,45.598 46.895,46.623 46.895,48.005 44.792,50.108 44.792,74.592 47.697,77.497 91.374,77.497 94.897,73.974 94.897,67.997 v1(92.4,65.5) 90.19,63.29 81.89,63.29 80.269,61.669 v1(78.306,61.669)
TEMP8_High: BMS_IC1_High.73 C8_High.1 J1_High.34 R10_High.1 | length 117.4
  Top Layer w0.3: C8_High.1@115.55,44.325 v1(116.25,44.325) R10_High.1@116.95,44.325 ; BMS_IC1_High.73@131.562,49.45 132.35,49.45 132.371,49.429 132.534,49.429 v1(132.559,49.404)
  Top Layer w0.5: v1(163.047,64.403) 163.504,63.946 164.944,63.946 J1_High.34@165.064,63.826
  Layer 2 w0.3: v1(132.559,49.404) 127.204,49.404 126.5,48.7 123.1,48.7 118.725,44.325 v1(116.25,44.325) 113.231,41.306 113.231,34.312 114.953,32.589 161.164,32.589 164.388,35.813 164.388,60.69 162.837,62.241 162.831,62.241 162.285,62.787 162.285,63.681 163.007,64.403 v1(163.047,64.403)
TEMP8_Low: BMS_IC1_Low.73 C8_Low.1 J1_Low.34 R10_Low.1 | length 116.8
  Top Layer w0.3: v1(76.22,61.167) 76.245,61.143 76.407,61.143 76.429,61.121 BMS_IC1_Low.73@77.217,61.121 ; R10_Low.1@91.7,64.2 v1(92.4,64.2) C8_Low.1@93.1,64.2
  Top Layer w0.5: J1_Low.34@43.715,46.745 43.835,46.625 45.275,46.625 v1(45.731,46.169)
  Layer 2 w0.3: v1(45.731,46.169) 45.772,46.169 46.494,46.89 46.494,47.784 45.947,48.331 45.941,48.331 44.39,49.882 44.39,74.758 47.53,77.898 91.54,77.898 95.298,74.14 95.298,67.098 v1(92.4,64.2) 91.002,62.802 84.002,62.802 83.173,61.973 82.173,61.973 81.367,61.167 v1(76.22,61.167)
TEMP9_High: BMS_IC1_High.72 C9_High.1 J1_High.31 R11_High.1 | length 124.7
  Top Layer w0.3: C9_High.1@115.55,45.625 116.225,45.625 v1(116.25,45.6) 116.263,45.613 R11_High.1@116.937,45.613 ; R11_High.1@116.912,45.687 R11_High.1@116.925,45.7 ; v1(130.501,49.906) 130.541,49.906 130.585,49.95 BMS_IC1_High.72@131.562,49.95
  Top Layer w0.7: J1_High.31@168.494,62.556 168.509,62.571 v1(170.479,62.571)
  Layer 2 w0.3: v1(130.501,49.906) 126.706,49.906 126.075,49.275 122.575,49.275 118.9,45.6 v1(116.25,45.6) 112.829,42.179 112.829,34.145 114.787,32.187 161.33,32.187 164.79,35.647 164.79,60.86 162.687,62.963 162.687,63.379 163.081,63.773 169.277,63.773 v1(170.479,62.571)
TEMP9_Low: BMS_IC1_Low.72 C9_Low.1 J1_Low.31 R11_Low.1 | length 124.1
  Top Layer w0.3: BMS_IC1_Low.72@77.217,60.621 78.208,60.621 78.237,60.651 v1(78.278,60.651) ; R11_Low.1@91.7,62.9 91.712,62.912 92.388,62.912 v1(92.4,62.925) 92.425,62.9 C9_Low.1@93.1,62.9
  Top Layer w0.7: v1(38.3,48) 40.27,48 J1_Low.31@40.285,48.015
  Layer 2 w0.3: v1(38.3,48) 39.502,46.798 45.698,46.798 46.092,47.192 46.092,47.608 43.989,49.711 43.989,74.925 47.364,78.3 91.707,78.3 95.7,74.307 95.7,66.225 v1(92.4,62.925) 91.775,62.3 84.1,62.3 83.371,61.571 82.403,61.571 81.534,60.702 78.434,60.702 78.413,60.68 78.307,60.68 v1(78.278,60.651)
TEMP10_High: BMS_IC1_High.71 C10_High.1 J1_High.32 R12_High.1 | length 120.8
  Top Layer w0.3: C10_High.1@115.55,46.925 v1(116.25,46.925) R12_High.1@116.95,46.925 ; BMS_IC1_High.71@131.562,50.45 132.609,50.45 132.659,50.5 v1(132.7,50.5)
  Top Layer w0.5: v1(163.211,63.149) 163.211,63.139 163.674,62.676 164.079,62.676 J1_High.32@164.199,62.556
  Top Layer w0.7: J1_High.32@164.199,62.556 J1_High.32@165.064,62.556
  Layer 2 w0.3: v1(132.7,50.5) 122.8,50.5 119.225,46.925 v1(116.25,46.925) 112.427,43.102 112.427,33.979 114.621,31.786 161.497,31.786 165.191,35.48 165.191,61.159 163.211,63.139 v1(163.211,63.149)
TEMP10_Low: BMS_IC1_Low.71 C10_Low.1 J1_Low.32 R12_Low.1 | length 120.3
  Top Layer w0.3: v1(76.079,60.071) 76.119,60.071 76.169,60.121 BMS_IC1_Low.71@77.217,60.121 ; R12_Low.1@91.7,61.6 v1(92.4,61.6) C10_Low.1@93.1,61.6
  Top Layer w0.5: J1_Low.32@44.58,48.015 44.7,47.895 45.105,47.895 45.568,47.432 v1(45.568,47.422)
  Top Layer w0.7: J1_Low.32@43.715,48.015 44.58,48.015 J1_Low.32@44.6,47.995
  Layer 2 w0.3: v1(45.568,47.422) 45.568,47.432 43.587,49.413 43.587,75.091 47.198,78.702 91.873,78.702 96.102,74.473 96.102,65.302 92.371,61.571 92.343,61.6 84,61.6 83.57,61.17 82.57,61.17 81.7,60.3 79.6,60.3 79.371,60.071 v1(76.079,60.071)
V+_High: BMS_IC1_High.1 C45_High.1 R66_High.2 | length 2.9
  Top Layer w0.3: BMS_IC1_High.1@133.55,43.962 133.55,42.3 C45_High.1@133.579,42.271 R66_High.2@133.579,41.071
V+_Low: BMS_IC1_Low.1 C45_Low.1 R66_Low.2 | length 2.9
  Top Layer w0.3: R66_Low.2@75.2,69.5 C45_Low.1@75.2,68.3 75.229,68.271 BMS_IC1_Low.1@75.229,66.609
Vref1_High: BMS_IC1_High.70 C40_High.2 | length 4.4
  Top Layer w0.3: C40_High.2@128.521,48.429 C40_High.2@128.523,48.43 ; C40_High.2@128.69,48.2 128.69,48.47 129.8,49.58 129.8,49.942 130.808,50.95 BMS_IC1_High.70@131.562,50.95
Vref1_Low: BMS_IC1_Low.70 C40_Low.2 | length 4.4
  Top Layer w0.3: BMS_IC1_Low.70@77.217,59.621 78.047,59.621 78.994,60.568 78.994,61.114 80.01,62.13 C40_Low.2@80.01,62.4
Vref2_High: BMS_IC1_High.68 C41_High.2 R3_High.2 R4_High.2 R5_High.2 R6_High.2 R7_High.2 R8_High.2 R9_High.2 R10_High.2 R11_High.2 R12_High.2 | length 28.7
  Top Layer w0.3: C41_High.2@128.69,51.8 128.79,51.9 v1(130.05,51.9) ; v1@130.071,51.929 130.093,51.95 BMS_IC1_High.68@131.562,51.95
  Top Layer w0.6: R3_High.2@118.325,35.35 118.325,36.525 118.325,37.825 118.325,39.125 118.325,40.425 118.325,41.725 118.325,43.025 118.325,44.325 R11_High.2@118.325,45.625 ; R11_High.2@118.35,45.625 R12_High.2@118.35,46.925 118.38,46.955 118.38,47.78 v1(118.4,47.8)
  Layer 2 w0.6: v1(118.4,47.8) 122.5,51.9 v1(130.05,51.9)
Vref2_Low: BMS_IC1_Low.68 C41_Low.2 R3_Low.2 R4_Low.2 R5_Low.2 R6_Low.2 R7_Low.2 R8_Low.2 R9_Low.2 R10_Low.2 R11_Low.2 R12_Low.2 | length 27.9
  Top Layer w0.3: BMS_IC1_Low.68@77.217,58.621 79.079,58.621 ccw(c79.079,58.671) v1(79.129,58.671) C41_Low.2@79.881,58.671 ; C41_Low.2@80.129,58.871 80.2,58.8 C41_Low.2@80.2,58.85 ; C41_Low.2@79.881,58.671 ccw(c79.881,58.8) C41_Low.2@80.01,58.8 ; C41_Low.2@79.881,58.671 ccw(c79.881,58.8) C41_Low.2@80.01,58.8 ; C41_Low.2@79.881,58.671 C41_Low.2@80.01,58.8
  Top Layer w0.6: v1(90.3,60.8) R12_Low.2@90.3,61.6 R11_Low.2@90.3,62.9 R10_Low.2@90.3,64.2 R9_Low.2@90.3,65.5 R8_Low.2@90.3,66.8 R7_Low.2@90.3,68.1 R6_Low.2@90.3,69.4 R5_Low.2@90.3,70.7 R4_Low.2@90.3,72 R3_Low.2@90.3,73.25
  Layer 2 w0.6: v1(79.129,58.671) 80.157,59.7 83.2,59.7 84.3,60.8 v1(90.3,60.8)
Vreg_High: BMS_IC1_High.60 BMS_IC1_High.69 C42_High.2 L1_High.2 | length 20.6
  Top Layer w0.3: C42_High.2@128.69,50 128.69,50.27 128.92,50.5 129.572,50.5 v1(130.161,51.089) ; v1@130.079,51.171 130.357,51.45 BMS_IC1_High.69@131.562,51.45 ; 132.305,51.45 133.1,52.245 133.1,56.293 133.55,56.743 BMS_IC1_High.60@133.55,57.438
  Top Layer w0.6: L1_High.2@124.554,45.571 124.604,45.521 124.954,45.521 124.976,45.5 128.6,45.5 v1(128.611,45.511)
  Bottom Layer w0.6: v1(128.611,45.511) 128.611,47.575 128.579,47.607 128.579,49.671 129.996,51.089 v1(130.161,51.089)
Vreg_Low: BMS_IC1_Low.60 BMS_IC1_Low.69 C42_Low.2 L1_Low.2 | length 20.2
  Top Layer w0.3: BMS_IC1_Low.60@75.229,53.133 75.229,53.829 75.679,54.279 75.679,58.327 76.473,59.121 ; BMS_IC1_Low.69@77.217,59.121 78.381,59.121 78.659,59.4 v1(78.7,59.4) 79.429,60.129 C42_Low.2@80.07,60.129
  Top Layer w0.6: v1(80.125,65.075) 80.2,65 L1_Low.2@84.225,65
  Bottom Layer w0.6: v1(78.7,59.4) 80.2,60.9 80.2,65 v1(80.125,65.075)
pads on no net: BMS_IC1_High.66 BMS_IC1_Low.66 J1_High.MH1 J1_High.MH2 J1_Low.MH1 J1_Low.MH2 J2.2 J2.4 J3.2 J3.4

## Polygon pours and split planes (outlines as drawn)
GND_High on Top Layer "GND_HIGH_L01_P042" (solid, pour order 42): 128.9,58.6 ccw(c128.3,58.6) 128.3,59.2 126.7,59.2 ccw(c126.7,58.9) 126.4,58.9 126.4,57.1 ccw(c126.7,57.1) 126.7,56.8 128.5,56.8 ccw(c128.5,57.2) 128.9,57.2
GND_High on Top Layer "GND_HIGH_L01_P041" (solid, pour order 41): 117.4,58.5 117.4,57.4 ccw(c117.9,57.4) 117.9,56.9 119.6,56.9 ccw(c119.6,57.4) 120.1,57.4 cw(c120.4,57.4) 120.4,57.7 122.6,57.7 ccw(c122.6,57.9) 122.8,57.9 122.8,59.5 ccw(c121.7,59.5) 121.7,60.6 119.074,60.6 ccw(c119.074,58.912) 117.386,58.912
GND_High on Top Layer "GND_HIGH_L01_P035" (solid, pour order 35): 141.9,56.6 cw(c141.9,54.4) 144.1,54.4 144.1,46.2 cw(c142.8,46.2) 142.8,44.9 135.4,44.9 cw(c135.4,47.2) 133.1,47.2 133.1,54.8 cw(c134.9,54.8) 134.9,56.6
GND_High on Top Layer "GND_HIGH_L01_P026" (solid, pour order 26): 127.2,53.55 127.2,47.65 125.9,47.65 cw(c125.9,47.85) 125.7,47.85 125.7,53.35 cw(c125.899,53.351) 125.9,53.55
GND_High on Top Layer "GND_HIGH_L01_P022" (solid, pour order 22): 125.301,68.2 127.2,68.2 cw(c127.2,67.9) 127.5,67.9 127.5,66.6 cw(c127.099,66.601) 127.1,66.2 125.3,66.2 cw(c125.3,66.5) 125,66.5 125,67.9 cw(c125.3,67.9)
GND_High on Top Layer "GND_HIGH_L01_P021" (solid, pour order 21): 114.3,47.3 cw(c114.3,47.2) 114.4,47.2 114.4,35.2 cw(c114.165,35.16) 114.205,34.925 111.5,34.925 cw(c111.437,35.262) 111.1,35.2 111.1,47.1 cw(c111.3,47.1) 111.3,47.3
GND_Low on Top Layer "GND_LOW_L01_P020" (solid, pour order 20): 65.7,63.976 cw(c66.724,63.976) 66,64.7 cw(c66.241,64.459) 66.241,64.8 74.276,64.8 cw(c74.276,63.776) 75,64.5 cw(c74.517,64.017) 75.2,64.017 75.2,55.524 cw(c74.176,55.524) 74.9,54.8 cw(c74.176,55.524) 74.176,54.5 66.824,54.5 cw(c66.824,55.524) 66.1,54.8 cw(c67.066,55.766) 65.7,55.766 65.7,60.7
GND_Low on Top Layer "GND_LOW_L01_P001" (solid, pour order 1): 94.4,61.3 cw(c94.4,61.4) 94.3,61.4 94.3,73.4 cw(c94.535,73.44) 94.495,73.675 97.2,73.675 cw(c97.263,73.338) 97.6,73.4 97.6,61.5 cw(c97.4,61.5) 97.4,61.3
GND_Low on Top Layer "GND_LOW_L01_P006" (solid, pour order 6): 85.901,56.7 87.4,56.7 cw(c87.4,56.4) 87.7,56.4 87.7,55 cw(c87.4,55) 87.4,54.7 85.9,54.7 cw(c85.9,55) 85.6,55 85.6,56.4 cw(c85.9,56.4)
GND_Low on Top Layer "GND_LOW_L01_P005" (solid, pour order 5): 87.7,44.1 ccw(c87.7,44.4) 88,44.4 88,46.6 ccw(c87.7,46.6) 87.7,46.9 86.067,46.9 ccw(c86.008,46.492) 85.6,46.55 85.6,44.5 ccw(c86,44.5) 86,44.1
GND_Low on Top Layer "GND_LOW_L01_P003" (solid, pour order 3): 77.2,50.3 77.2,49.9 ccw(c77.5,49.9) 77.5,49.6 79.6,49.6 ccw(c79.529,49.771) 79.7,49.7 79.7,50.5 ccw(c79.46,50.46) 79.5,50.7 77.6,50.7 ccw(c77.6,50.3)
GND_Low on Top Layer "GND_LOW_L01_P000" (solid, pour order 0): 81.5,57 81.5,62.9 82.8,62.9 cw(c82.8,62.7) 83,62.7 83,57.2 cw(c82.801,57.199) 82.8,57
GND_Low on Layer 1 "GND_LOW_L02_P038" (solid, pour order 38): 38.565,79 ccw(c38.565,76.435) 36,76.435 36,33.065 ccw(c38.565,33.065) 38.565,30.5 79.435,30.5 ccw(c79.435,33.065) 82,33.065 82,38.535 cw(c84.565,38.535) 84.565,41.1 87.6,41.1 ccw(c87.6,42.3) 88.8,42.3 88.8,57.035 cw(c91.365,57.035) 91.365,59.6 98.061,59.699 ccw(c95.832,62.489) 99.1,61.05 99.1,78.3 ccw(c98.174,78.074) 98.4,79
GND_High on Layer 1 "GND_HIGH_L02_P039" (solid, pour order 39): 174.5,76.935 ccw(c171.935,76.935) 171.935,79.5 124.307,79.393 ccw(c124.307,76.586) 121.5,76.586 121.5,67.2 cw(c119.7,67.1) 119.8,65.3 115.7,65.3 ccw(c115.6,63.8) 114.1,63.9 114.1,51 cw(c112.4,51) 112.4,49.3 111.6,49.3 ccw(c111.6,48.2) 110.5,48.2 110.5,31.3 ccw(c111.4,31.3) 111.4,30.4 171.935,30.4 ccw(c171.935,32.965) 174.5,32.965
GND_Low on Layer 2 "GND_LOW_L03_P044" (solid, pour order 44): 38.565,79.502 ccw(c38.817,76.686) 36,76.435 36,33.065 ccw(c38.565,33.065) 38.565,30.5 79.435,30.5 ccw(c79.435,33.065) 82,33.065 82,38.535 cw(c84.565,38.535) 84.565,41.1 87.6,41.1 ccw(c87.6,42.3) 88.8,42.3 88.8,57.035 cw(c91.365,57.035) 91.365,59.6 98.061,59.699 ccw(c95.832,62.489) 99.1,61.05 99.1,78.7 ccw(c98.038,78.441) 98.298,79.502
GND_High on Layer 2 "GND_HIGH_L03_P043" (solid, pour order 43): 174.5,76.935 ccw(c171.935,76.935) 171.935,79.5 124.307,79.393 ccw(c124.307,76.586) 121.5,76.586 121.5,67.2 cw(c119.7,67.1) 119.8,65.3 115.7,65.3 ccw(c115.6,63.8) 114.1,63.9 114.1,51 cw(c112.4,51) 112.4,49.3 111.6,49.3 ccw(c111.6,48.2) 110.5,48.2 110.5,31.3 ccw(c111.4,31.3) 111.4,30.4 171.935,30.4 ccw(c171.935,32.965) 174.5,32.965

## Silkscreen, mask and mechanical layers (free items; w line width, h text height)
Top Overlay:
  drawing of 20 lines, arcs and shapes, not listed
  text "1" at 128.2,78.3 h1
  text "3" at 131.4,78.3 h1
  text "5" at 134.7,78.3 h1
  text "9" at 141.6,78.3 h1
  text "11" at 144.7,78.3 h1
  text "13" at 148,78.3 h1
  text "7" at 138.3,78.2 h1
  text "ADI Daugherboard" at 86.7,77.933 h1
  text "March 2025" at 108.5,77.6 h1
  text "Balancing" at 151.7,74.833 h1
  text "Temps" at 90,74.433 h1
  text "1" at 95.25,73.05 h0.5
  text "Drake" at 99.5,72.7 h1
  text "2" at 95.15,71.75 h0.5
  text "C23" at 70.35,71.45 h0.5
  text "Vogelpohl" at 99.6,71.133 h1
  text "C22" at 65.475,70.85 h0.5
  text "6" at 136.5,70.7 h1
  text "2" at 129.7,70.6 h1
  text "4" at 133,70.6 h1
  text "8" at 139.9,70.6 h1
  text "10" at 142.9,70.6 h1
  text "12" at 146.3,70.6 h1
  text "14" at 149.8,70.5 h1
  text "3" at 95.15,70.45 h0.5
  text "C21" at 61.65,69.75 h0.5
  text "4" at 95.15,69.15 h0.5
  text "C24" at 69.879,69.121 h0.5
  text "5" at 95.15,67.85 h0.5
  text "HIGH" at 158.73,67.419 h2 r180
  text "6" at 95.15,66.45 h0.5
  text "7" at 95.15,65.25 h0.5
  text "C20" at 59.414,64.15 h0.5 r90
  text "8" at 95.15,63.95 h0.5
  text "C11" at 133.35,62.85 h0.5
  text "9" at 95.15,62.75 h0.5
  text "C13" at 137.229,62.721 h0.5
  text "HIGH" at 151.768,62.582 h2
  text "C12" at 134.65,61.45 h0.5
  text "C14" at 138.55,61.45 h0.5
  text "10" at 95.15,61.35 h0.5
  text "C19" at 61.65,60.95 h0.5 r90
  text "C15" at 146.65,59.45 h0.5
  text "C17" at 61.55,57.45 h0.5 r90
  text "C18" at 59.25,56.75 h0.5 r90
  text "C16" at 148.65,56.35 h0.5 r90
  text "C16" at 61.65,54.85 h0.5 r90
  text "C18" at 149.913,52.55 h0.5 r90
  text "C17" at 147.75,51.85 h0.5 r90
  text "C15" at 60.95,50.65 h0.5
  text "C12" at 68.97,48.675 h0.5
  text "C19" at 147.775,48.6 h0.5 r90
  text "C14" at 65.15,48.55 h0.5
  text "LOW" at 55.2,47.5 h2 r180
  text "C11" at 70.55,47.35 h0.5
  text "C13" at 66.35,47.25 h0.5
  text "10" at 112.85,46.65 h0.5
  text "9" at 113.25,45.35 h0.5
  text "C20" at 149.95,45.15 h0.5 r90
  text "8" at 113.25,44.05 h0.5
  text "7" at 113.25,42.75 h0.5
  text "LOW" at 49.842,42.655 h2
  text "C21" at 145.829,41.621 h0.5 r90
  text "6" at 113.15,41.45 h0.5
  text "5" at 113.15,40.15 h0.5
  text "C24" at 139.629,40.071 h0.5
  text "C22" at 143.529,40.021 h0.5
  text "4" at 113.15,38.85 h0.5
  text "C23" at 140.95,38.75 h0.5
  text "13" at 59.4,38.3 h1
  text "11" at 62.9,38.3 h1
  text "9" at 66.5,38.3 h1
  text "7" at 70.2,38.3 h1
  text "5" at 73.3,38.3 h1
  text "3" at 76.8,38.3 h1
  text "1" at 80.3,38.3 h1
  text "3" at 113.25,37.55 h0.5
  text "2" at 113.25,36.25 h0.5
  text "1" at 113.35,34.95 h0.5
  text "Balancing" at 48.9,34.133 h1
  text "Temps" at 114.1,33.333 h1
  text "14" at 57.7,30.8 h1
  text "12" at 61.1,30.8 h1
  text "10" at 64.5,30.8 h1
  text "8" at 68.3,30.8 h1
  text "6" at 71.6,30.8 h1
  text "4" at 75.1,30.8 h1
  text "2" at 78.5,30.8 h1
Mechanical 1:
  lines w0.254: 171.586,29.986 ccw(c171.586,33.4) 175,33.4 ; 171.586,30 38.414,30 cw(c38.414,33.414) 35,33.414 35,76.586 cw(c38.414,76.586) 38.414,80 171.586,80 cw(c171.586,76.586) 175,76.586 175,33.414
